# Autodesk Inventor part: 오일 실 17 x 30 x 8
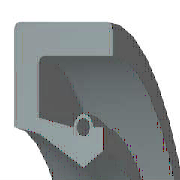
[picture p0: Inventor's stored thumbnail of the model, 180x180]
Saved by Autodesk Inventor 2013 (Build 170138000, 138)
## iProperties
IsCustomPart: 1
Created: 2012-02
Part Number: 오일 실 17 x 30 x 8
Material: 고무
Description: 오일 실 - 스프링 장착, 금속 케이스 SM
Document SubType Name: Modeling
Standard: JIS B 2402
Designer: mdu-01
Standards Organization: JIS
Language: ko-KR
Size Designation: 17 30 8 A
Categories: <MemberInstance><Categories><Category DisplayName="샤프트 부품" InternalName="7f7aeb1f-a693-4053-b835-cee3144e0d98" Mnemonic="SHFT"><Category DisplayName="실링" Intern
Density: 0.93 g/cm^3
Author: mdu-01
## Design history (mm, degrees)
body "Solid1"
revolve "회전1" stored, may be unused: angle "d33" = 360 deg
fillet "모깎기1" dims "d34" = 0.4 (= 0.05 x b)
chamfer "모따기1" distance "d35" = 0.8 (= 0.1 x b); stored, may be unused: second distance "d36" = 0.4 (= 0.05 x b), angle "d41" = 45 deg
sketch "스케치2"
  geometry: L1 (10.079, -5.895)-(10.689, -8); L2 (9.429, -5.2)-(10.079, -5.895); L3 (8.5, -2)-(9.429, -5.2); L4 (9.367, -1)-(8.5, -2); L5 (10.819, -1)-(9.367, -1); L6 (10.819, -1.8)-(10.819, -1); L7 (10.819, -6)-(10.819, -3.4); L8 (12.4, -6)-(10.819, -6); L9 (13.7, -2)-(12.4, -6); L10 (13.7, 0)-(13.7, -2); L11 (15, 0)-(13.7, 0); L12 (15, -8)-(15, 0); L13 (10.689, -8)-(15, -8); L14 (0, -9.6)-(0, 1.6) reference; L15 (28, 0)-(14, 0) reference; A1 r 0.8 centre (10.819, -2.6) between (10.819, -3.4) and (10.819, -1.8)
  constraints: 26 end point, 4 horizontal, 4 vertical, 2 point on circle, 1 centre point, 1 collinear, 1 parallel
  dimensions: "d2" = 8 distance of L12.start L11.start (= b); "d4" = 1 vertical distance of L10.start L5.start (= 0.125 x b); "d6" = 1.3 distance of L11.start L10.start (= 0.1 x dd - 0.1 x Diam); "d8" = 2 distance of L10.start L9.start (= 0.25 x b); "d10" = 2 vertical distance of L8.start L1.end (= 0.25 x b); "d12" = 1.3 horizontal distance of L9.start L8.start (= 0.1 x dd - 0.1 x Diam); "d14" = 0.8 radius of A1 (= 0.1 x b); "d16" = 0 horizontal distance of A1.centre L7.end; "d18" = 0.8 distance of L6.start L5.start (= 0.1 x b); "d20" = 0.86667 horizontal distance of L4.start L3.start (= 0.0666667 x dd - 0.0666667 x Diam); "d22" = 0.13 horizontal distance of L7.start L1.end (= 0.01 x dd - 0.01 x Diam); "d24" = 1 vertical distance of L4.start L3.start (= 0.125 x b); "d26" = 3.2 vertical distance of L3.start L2.start (= 0.4 x b); "d28" = 0.92857 horizontal distance of L3.start L2.start (= 0.0714286 x dd - 0.0714286 x Diam); "d30" = 2.10526 vertical distance of L1.start L1.end (= 0.263158 x b); "d32" = 0.65 horizontal distance of L2.start L1.start (= 0.05 x dd - 0.05 x Diam); "d37" = 0 distance between parallel lines of L15 L11; "d38" = 15 distance between parallel lines of L14 L12 (= 0.5 x dd); "d39" = 8.5 distance from line of L14 L3.start (= 0.5 x Diam)
other parameters: "Diam" = 17 [user parameter; used in 7 equation terms], "b" = 8 [user parameter; used in 12 equation terms], "d1" = 8 (derived), "d3" = 1 (derived), "d5" = 2 (derived), "d7" = 2 (derived), "d9" = 2 (derived), "d11" = 2 (derived), "d13" = 0.8 (derived), "d15" = 0 (derived), "d17" = 0.8 (derived), "d19" = 1.33333 (derived), "d21" = 0.2 (derived), "d23" = 1 (derived), "d25" = 3.2 (derived), "d27" = 1.42857 (derived), "d29" = 2.10526 (derived), "d31" = 1 (derived), "d40" = 0
